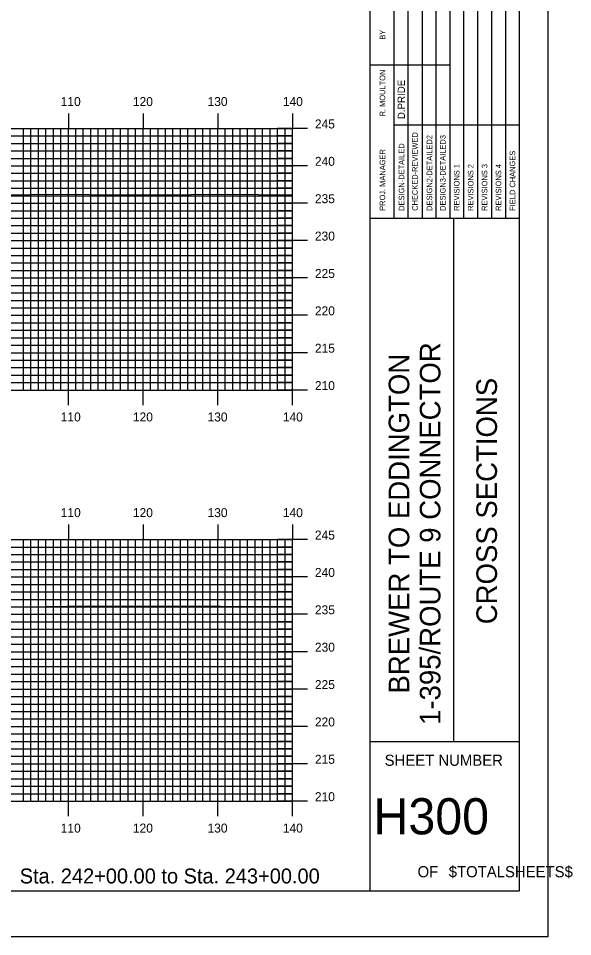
# Model space of a CAD drawing. Extents: x 1802323 to 1802666, y 442591 to 442811.
# Drawn here: x 1802591.9 to 1802666.1, y 442590.5 to 442713.4 of the extents above; entities that cross this region are included whole.
import ezdxf

# ---------------------------------------------------------------- set-up
doc = ezdxf.new("R2010")
doc.units = 0
for name, color, linetype in [('BORDER', 7, 'Continuous'), ('H_V ANNOTATION', 7, 'Continuous'), ('MAJOR', 7, 'Continuous'), ('MINOR', 7, 'Continuous'), ('PLOT BOUNDARY', 7, 'Continuous'), ('S_Roadway_Centerline', 7, 'Continuous')]:
    doc.layers.add(name, color=color, linetype=linetype)

msp = doc.modelspace()

# ---------------------------------------------------------------- linework, layer by layer
at = {"layer": 'BORDER'}
for p, q in [((1802639, 442596.67), (1802639, 442806.67)), ((1802639, 442686.67), (1802659, 442686.67)), ((1802650.18, 442616.67), (1802650.18, 442686.67)), ((1802639, 442616.67), (1802659, 442616.67))]:
    msp.add_line(p, q, dxfattribs=at)
msp.add_lwpolyline([(1802339, 442596.67), (1802659, 442596.67), (1802659, 442806.67), (1802339, 442806.67)], close=True, dxfattribs=at)
for points in [[(1802644.1, 442686.68), (1802644.1, 442721.67)], [(1802645.96, 442721.67), (1802645.96, 442686.68)], [(1802647.82, 442686.68), (1802647.82, 442721.67)], [(1802649.69, 442686.68), (1802649.69, 442721.67)], [(1802651.55, 442686.68), (1802651.55, 442721.67)], [(1802653.41, 442686.68), (1802653.41, 442721.67)], [(1802655.28, 442686.68), (1802655.28, 442721.67)], [(1802657.14, 442686.68), (1802657.14, 442721.67)], [(1802642.23, 442686.68), (1802642.23, 442720.26)], [(1802639, 442707.17), (1802642.23, 442707.17)], [(1802642.23, 442707.17), (1802649.68, 442707.17)], [(1802642.23, 442699.17), (1802659, 442699.17)]]:
    msp.add_lwpolyline(points, dxfattribs=at)
at = {"layer": 'MAJOR'}
for p, q in [((1802598.6, 442700.67), (1802598.6, 442698.67)), ((1802608.6, 442700.67), (1802608.6, 442698.67)), ((1802618.6, 442700.67), (1802618.6, 442698.67)), ((1802628.6, 442700.67), (1802628.6, 442698.67)), ((1802348.6, 442698.67), (1802628.6, 442698.67)), ((1802348.6, 442698.67), (1802628.6, 442698.67)), ((1802598.6, 442663.67), (1802598.6, 442698.67)), ((1802608.6, 442663.67), (1802608.6, 442698.67)), ((1802618.6, 442663.67), (1802618.6, 442698.67)), ((1802630.61, 442698.67), (1802626.6, 442698.67)), ((1802628.6, 442663.67), (1802628.6, 442698.67)), ((1802628.6, 442663.67), (1802628.6, 442698.67)), ((1802348.6, 442693.67), (1802628.6, 442693.67)), ((1802630.61, 442693.67), (1802626.6, 442693.67)), ((1802348.6, 442688.67), (1802628.6, 442688.67)), ((1802630.61, 442688.67), (1802626.6, 442688.67)), ((1802348.6, 442683.67), (1802628.6, 442683.67)), ((1802630.61, 442683.67), (1802626.6, 442683.67)), ((1802348.6, 442678.67), (1802628.6, 442678.67)), ((1802630.61, 442678.67), (1802626.6, 442678.67)), ((1802348.6, 442673.67), (1802628.6, 442673.67)), ((1802630.61, 442673.67), (1802626.6, 442673.67)), ((1802348.6, 442668.67), (1802628.6, 442668.67)), ((1802630.61, 442668.67), (1802626.6, 442668.67)), ((1802348.6, 442663.67), (1802628.6, 442663.67)), ((1802348.6, 442663.67), (1802628.6, 442663.67)), ((1802598.6, 442661.66), (1802598.6, 442663.67)), ((1802608.6, 442661.66), (1802608.6, 442663.67)), ((1802618.6, 442661.66), (1802618.6, 442663.67)), ((1802630.61, 442663.67), (1802626.6, 442663.67)), ((1802628.6, 442661.66), (1802628.6, 442663.67)), ((1802598.6, 442645.67), (1802598.6, 442643.67)), ((1802608.6, 442645.67), (1802608.6, 442643.67)), ((1802618.6, 442645.67), (1802618.6, 442643.67)), ((1802628.6, 442645.67), (1802628.6, 442643.67)), ((1802348.6, 442643.67), (1802628.6, 442643.67)), ((1802348.6, 442643.67), (1802628.6, 442643.67)), ((1802598.6, 442608.67), (1802598.6, 442643.67)), ((1802608.6, 442608.67), (1802608.6, 442643.67)), ((1802618.6, 442608.67), (1802618.6, 442643.67)), ((1802630.61, 442643.67), (1802626.6, 442643.67)), ((1802628.6, 442608.67), (1802628.6, 442643.67)), ((1802628.6, 442608.67), (1802628.6, 442643.67)), ((1802348.6, 442638.67), (1802628.6, 442638.67)), ((1802630.61, 442638.67), (1802626.6, 442638.67)), ((1802348.6, 442633.67), (1802628.6, 442633.67)), ((1802630.61, 442633.67), (1802626.6, 442633.67)), ((1802348.6, 442628.67), (1802628.6, 442628.67)), ((1802630.61, 442628.67), (1802626.6, 442628.67)), ((1802348.6, 442623.67), (1802628.6, 442623.67)), ((1802630.61, 442623.67), (1802626.6, 442623.67)), ((1802348.6, 442618.67), (1802628.6, 442618.67)), ((1802630.61, 442618.67), (1802626.6, 442618.67)), ((1802348.6, 442613.67), (1802628.6, 442613.67)), ((1802630.61, 442613.67), (1802626.6, 442613.67)), ((1802348.6, 442608.67), (1802628.6, 442608.67)), ((1802348.6, 442608.67), (1802628.6, 442608.67)), ((1802598.6, 442606.66), (1802598.6, 442608.67)), ((1802608.6, 442606.66), (1802608.6, 442608.67)), ((1802618.6, 442606.66), (1802618.6, 442608.67)), ((1802630.61, 442608.67), (1802626.6, 442608.67)), ((1802628.6, 442606.66), (1802628.6, 442608.67))]:
    msp.add_line(p, q, dxfattribs=at)
at = {"layer": 'MINOR'}
for p, q in [((1802592.6, 442663.67), (1802592.6, 442698.67)), ((1802593.6, 442663.67), (1802593.6, 442698.67)), ((1802594.6, 442663.67), (1802594.6, 442698.67)), ((1802595.6, 442663.67), (1802595.6, 442698.67)), ((1802596.6, 442663.67), (1802596.6, 442698.67)), ((1802597.6, 442663.67), (1802597.6, 442698.67)), ((1802599.6, 442663.67), (1802599.6, 442698.67)), ((1802600.6, 442663.67), (1802600.6, 442698.67)), ((1802601.6, 442663.67), (1802601.6, 442698.67)), ((1802602.6, 442663.67), (1802602.6, 442698.67)), ((1802603.6, 442663.67), (1802603.6, 442698.67)), ((1802604.6, 442663.67), (1802604.6, 442698.67)), ((1802605.6, 442663.67), (1802605.6, 442698.67)), ((1802606.6, 442663.67), (1802606.6, 442698.67)), ((1802607.6, 442663.67), (1802607.6, 442698.67)), ((1802609.6, 442663.67), (1802609.6, 442698.67)), ((1802610.6, 442663.67), (1802610.6, 442698.67)), ((1802611.6, 442663.67), (1802611.6, 442698.67)), ((1802612.6, 442663.67), (1802612.6, 442698.67)), ((1802613.6, 442663.67), (1802613.6, 442698.67)), ((1802614.6, 442663.67), (1802614.6, 442698.67)), ((1802615.6, 442663.67), (1802615.6, 442698.67)), ((1802616.6, 442663.67), (1802616.6, 442698.67)), ((1802617.6, 442663.67), (1802617.6, 442698.67)), ((1802619.6, 442663.67), (1802619.6, 442698.67)), ((1802620.6, 442663.67), (1802620.6, 442698.67)), ((1802621.6, 442663.67), (1802621.6, 442698.67)), ((1802622.6, 442663.67), (1802622.6, 442698.67)), ((1802623.6, 442663.67), (1802623.6, 442698.67)), ((1802624.6, 442663.67), (1802624.6, 442698.67)), ((1802625.6, 442663.67), (1802625.6, 442698.67)), ((1802626.6, 442663.67), (1802626.6, 442698.67)), ((1802627.6, 442663.67), (1802627.6, 442698.67)), ((1802348.6, 442697.67), (1802628.6, 442697.67)), ((1802628.6, 442697.67), (1802626.6, 442697.67)), ((1802348.6, 442696.67), (1802628.6, 442696.67)), ((1802628.6, 442696.67), (1802626.6, 442696.67)), ((1802348.6, 442695.67), (1802628.6, 442695.67)), ((1802628.6, 442695.67), (1802626.6, 442695.67)), ((1802348.6, 442694.67), (1802628.6, 442694.67)), ((1802628.6, 442694.67), (1802626.6, 442694.67)), ((1802348.6, 442692.67), (1802628.6, 442692.67)), ((1802628.6, 442692.67), (1802626.6, 442692.67)), ((1802348.6, 442691.67), (1802628.6, 442691.67)), ((1802628.6, 442691.67), (1802626.6, 442691.67)), ((1802348.6, 442690.67), (1802628.6, 442690.67)), ((1802628.6, 442690.67), (1802626.6, 442690.67)), ((1802348.6, 442689.67), (1802628.6, 442689.67)), ((1802628.6, 442689.67), (1802626.6, 442689.67)), ((1802348.6, 442687.67), (1802628.6, 442687.67)), ((1802628.6, 442687.67), (1802626.6, 442687.67)), ((1802348.6, 442686.67), (1802628.6, 442686.67)), ((1802628.6, 442686.67), (1802626.6, 442686.67)), ((1802348.6, 442685.67), (1802628.6, 442685.67)), ((1802628.6, 442685.67), (1802626.6, 442685.67)), ((1802348.6, 442684.67), (1802628.6, 442684.67)), ((1802628.6, 442684.67), (1802626.6, 442684.67)), ((1802348.6, 442682.67), (1802628.6, 442682.67)), ((1802628.6, 442682.67), (1802626.6, 442682.67)), ((1802348.6, 442681.67), (1802628.6, 442681.67)), ((1802628.6, 442681.67), (1802626.6, 442681.67)), ((1802348.6, 442680.67), (1802628.6, 442680.67)), ((1802628.6, 442680.67), (1802626.6, 442680.67)), ((1802348.6, 442679.67), (1802628.6, 442679.67)), ((1802628.6, 442679.67), (1802626.6, 442679.67)), ((1802348.6, 442677.67), (1802628.6, 442677.67)), ((1802628.6, 442677.67), (1802626.6, 442677.67)), ((1802348.6, 442676.67), (1802628.6, 442676.67)), ((1802628.6, 442676.67), (1802626.6, 442676.67)), ((1802348.6, 442675.67), (1802628.6, 442675.67)), ((1802628.6, 442675.67), (1802626.6, 442675.67)), ((1802348.6, 442674.67), (1802628.6, 442674.67)), ((1802628.6, 442674.67), (1802626.6, 442674.67)), ((1802348.6, 442672.67), (1802628.6, 442672.67)), ((1802628.6, 442672.67), (1802626.6, 442672.67)), ((1802348.6, 442671.67), (1802628.6, 442671.67)), ((1802628.6, 442671.67), (1802626.6, 442671.67)), ((1802348.6, 442670.67), (1802628.6, 442670.67)), ((1802628.6, 442670.67), (1802626.6, 442670.67)), ((1802348.6, 442669.67), (1802628.6, 442669.67)), ((1802628.6, 442669.67), (1802626.6, 442669.67)), ((1802348.6, 442667.67), (1802628.6, 442667.67)), ((1802348.6, 442666.67), (1802628.6, 442666.67)), ((1802628.6, 442667.67), (1802626.6, 442667.67)), ((1802628.6, 442666.67), (1802626.6, 442666.67)), ((1802348.6, 442665.67), (1802628.6, 442665.67)), ((1802628.6, 442665.67), (1802626.6, 442665.67)), ((1802348.6, 442664.67), (1802628.6, 442664.67)), ((1802628.6, 442664.67), (1802626.6, 442664.67)), ((1802592.6, 442608.67), (1802592.6, 442643.67)), ((1802593.6, 442608.67), (1802593.6, 442643.67)), ((1802594.6, 442608.67), (1802594.6, 442643.67)), ((1802595.6, 442608.67), (1802595.6, 442643.67)), ((1802596.6, 442608.67), (1802596.6, 442643.67)), ((1802597.6, 442608.67), (1802597.6, 442643.67)), ((1802599.6, 442608.67), (1802599.6, 442643.67)), ((1802600.6, 442608.67), (1802600.6, 442643.67)), ((1802601.6, 442608.67), (1802601.6, 442643.67)), ((1802602.6, 442608.67), (1802602.6, 442643.67)), ((1802603.6, 442608.67), (1802603.6, 442643.67)), ((1802604.6, 442608.67), (1802604.6, 442643.67)), ((1802605.6, 442608.67), (1802605.6, 442643.67)), ((1802606.6, 442608.67), (1802606.6, 442643.67)), ((1802607.6, 442608.67), (1802607.6, 442643.67)), ((1802609.6, 442608.67), (1802609.6, 442643.67)), ((1802610.6, 442608.67), (1802610.6, 442643.67)), ((1802611.6, 442608.67), (1802611.6, 442643.67)), ((1802612.6, 442608.67), (1802612.6, 442643.67)), ((1802613.6, 442608.67), (1802613.6, 442643.67)), ((1802614.6, 442608.67), (1802614.6, 442643.67)), ((1802615.6, 442608.67), (1802615.6, 442643.67)), ((1802616.6, 442608.67), (1802616.6, 442643.67)), ((1802617.6, 442608.67), (1802617.6, 442643.67)), ((1802619.6, 442608.67), (1802619.6, 442643.67)), ((1802620.6, 442608.67), (1802620.6, 442643.67)), ((1802621.6, 442608.67), (1802621.6, 442643.67)), ((1802622.6, 442608.67), (1802622.6, 442643.67)), ((1802623.6, 442608.67), (1802623.6, 442643.67)), ((1802624.6, 442608.67), (1802624.6, 442643.67)), ((1802625.6, 442608.67), (1802625.6, 442643.67)), ((1802626.6, 442608.67), (1802626.6, 442643.67)), ((1802627.6, 442608.67), (1802627.6, 442643.67)), ((1802348.6, 442642.67), (1802628.6, 442642.67)), ((1802628.6, 442642.67), (1802626.6, 442642.67)), ((1802348.6, 442641.67), (1802628.6, 442641.67)), ((1802628.6, 442641.67), (1802626.6, 442641.67)), ((1802348.6, 442640.67), (1802628.6, 442640.67)), ((1802348.6, 442639.67), (1802628.6, 442639.67)), ((1802628.6, 442640.67), (1802626.6, 442640.67)), ((1802628.6, 442639.67), (1802626.6, 442639.67)), ((1802348.6, 442637.67), (1802628.6, 442637.67)), ((1802628.6, 442637.67), (1802626.6, 442637.67)), ((1802348.6, 442636.67), (1802628.6, 442636.67)), ((1802628.6, 442636.67), (1802626.6, 442636.67)), ((1802348.6, 442635.67), (1802628.6, 442635.67)), ((1802348.6, 442634.67), (1802628.6, 442634.67)), ((1802628.6, 442635.67), (1802626.6, 442635.67)), ((1802628.6, 442634.67), (1802626.6, 442634.67)), ((1802348.6, 442632.67), (1802628.6, 442632.67)), ((1802628.6, 442632.67), (1802626.6, 442632.67)), ((1802348.6, 442631.67), (1802628.6, 442631.67)), ((1802628.6, 442631.67), (1802626.6, 442631.67)), ((1802348.6, 442630.67), (1802628.6, 442630.67)), ((1802628.6, 442630.67), (1802626.6, 442630.67)), ((1802348.6, 442629.67), (1802628.6, 442629.67)), ((1802628.6, 442629.67), (1802626.6, 442629.67)), ((1802348.6, 442627.67), (1802628.6, 442627.67)), ((1802628.6, 442627.67), (1802626.6, 442627.67)), ((1802348.6, 442626.67), (1802628.6, 442626.67)), ((1802628.6, 442626.67), (1802626.6, 442626.67)), ((1802348.6, 442625.67), (1802628.6, 442625.67)), ((1802628.6, 442625.67), (1802626.6, 442625.67)), ((1802348.6, 442624.67), (1802628.6, 442624.67)), ((1802628.6, 442624.67), (1802626.6, 442624.67)), ((1802348.6, 442622.67), (1802628.6, 442622.67)), ((1802628.6, 442622.67), (1802626.6, 442622.67)), ((1802348.6, 442621.67), (1802628.6, 442621.67)), ((1802628.6, 442621.67), (1802626.6, 442621.67)), ((1802348.6, 442620.67), (1802628.6, 442620.67)), ((1802628.6, 442620.67), (1802626.6, 442620.67)), ((1802348.6, 442619.67), (1802628.6, 442619.67)), ((1802628.6, 442619.67), (1802626.6, 442619.67)), ((1802348.6, 442617.67), (1802628.6, 442617.67)), ((1802628.6, 442617.67), (1802626.6, 442617.67)), ((1802348.6, 442616.67), (1802628.6, 442616.67)), ((1802628.6, 442616.67), (1802626.6, 442616.67)), ((1802348.6, 442615.67), (1802628.6, 442615.67)), ((1802628.6, 442615.67), (1802626.6, 442615.67)), ((1802348.6, 442614.67), (1802628.6, 442614.67)), ((1802628.6, 442614.67), (1802626.6, 442614.67)), ((1802348.6, 442612.67), (1802628.6, 442612.67)), ((1802628.6, 442612.67), (1802626.6, 442612.67)), ((1802348.6, 442611.67), (1802628.6, 442611.67)), ((1802628.6, 442611.67), (1802626.6, 442611.67)), ((1802348.6, 442610.67), (1802628.6, 442610.67)), ((1802628.6, 442610.67), (1802626.6, 442610.67)), ((1802348.6, 442609.67), (1802628.6, 442609.67)), ((1802628.6, 442609.67), (1802626.6, 442609.67))]:
    msp.add_line(p, q, dxfattribs=at)
at = {"layer": 'PLOT BOUNDARY'}
msp.add_lwpolyline([(1802322.81, 442590.55), (1802662.81, 442590.55), (1802662.81, 442810.55), (1802322.81, 442810.55)], close=True, dxfattribs=at)
at = {"layer": 'S_Roadway_Centerline'}
for points in [[(1802507.23, 442689.68), (1802521.77, 442689.85), (1802532.92, 442689.56), (1802542.65, 442689.58), (1802558.19, 442689.59), (1802561.43, 442689.59), (1802563.86, 442689.58), (1802573.13, 442689.67), (1802584.23, 442689.67), (1802585.29, 442689.69), (1802596.5, 442689.86), (1802606.34, 442689.81), (1802608.02, 442689.8), (1802610.12, 442689.78), (1802619.94, 442689.88), (1802628.21, 442689.81), (1802628.6, 442689.81)], [(1802516.07, 442634.75), (1802519.95, 442634.88), (1802523.24, 442635.01), (1802541.26, 442634.25), (1802543.67, 442634.08), (1802558.29, 442634.4), (1802565.52, 442634.56), (1802566.08, 442634.55), (1802566.8, 442634.53), (1802586.57, 442634.64), (1802588.92, 442634.72), (1802592.53, 442634.68), (1802601.35, 442634.81), (1802607.76, 442634.75), (1802618.96, 442634.77), (1802628.6, 442634.72)]]:
    msp.add_lwpolyline(points, dxfattribs=at)

# ---------------------------------------------------------------- texts
at = {"layer": 'BORDER'}
for s, height, p in [('BY', 0.743, (1802641.01, 442710.54)), ('R. MOULTON', 0.745, (1802641.01, 442700.28)), ('D.PRIDE', 0.969, (1802643.65, 442699.92)), ('CHECKED-REVIEWED', 0.7455, (1802645.36, 442687.65)), ('DESIGN2-DETAILED2', 0.7455, (1802647.3, 442687.65)), ('DESIGN3-DETAILED3', 0.7455, (1802649.09, 442687.65)), ('DESIGN-DETAILED', 0.7455, (1802643.57, 442687.65)), ('PROJ. MANAGER', 0.7455, (1802641.01, 442687.65)), ('FIELD CHANGES', 0.7455, (1802658.41, 442687.65)), ('REVISIONS 1', 0.7455, (1802650.95, 442687.65)), ('REVISIONS 2', 0.7455, (1802652.82, 442687.65)), ('REVISIONS 3', 0.7455, (1802654.68, 442687.65)), ('REVISIONS 4', 0.7455, (1802656.54, 442687.65)), ('1-395/ROUTE 9 CONNECTOR', 2.7557, (1802648.4, 442618.87)), ('BREWER TO EDDINGTON', 2.7557, (1802644.23, 442623.07)), ('CROSS SECTIONS', 2.7557, (1802655.97, 442632.34))]:
    msp.add_text(s, height=height, rotation=90, dxfattribs=at).set_placement(p)
for s, height, p in [('SHEET NUMBER', 1.4905, (1802640.93, 442613.4)), ('H300', 4.839, (1802639.44, 442604.23)), ('OF', 1.491, (1802645.34, 442598.49)), ('$TOTALSHEETS$', 1.4905, (1802649.51, 442598.49))]:
    msp.add_text(s, height=height, dxfattribs=at).set_placement(p)
at = {"layer": 'H_V ANNOTATION'}
for s, height, p in [('110', 1.2, (1802597.58, 442701.67)), ('120', 1.2, (1802607.24, 442701.67)), ('130', 1.2, (1802617.23, 442701.67)), ('140', 1.2, (1802627.31, 442701.67)), ('245', 1.2, (1802631.6, 442698.67)), ('240', 1.2, (1802631.6, 442693.67)), ('235', 1.2, (1802631.6, 442688.67)), ('230', 1.2, (1802631.6, 442683.67)), ('225', 1.2, (1802631.6, 442678.67)), ('220', 1.2, (1802631.6, 442673.67)), ('215', 1.2, (1802631.6, 442668.67)), ('210', 1.2, (1802631.6, 442663.67)), ('110', 1.2, (1802597.58, 442659.47)), ('120', 1.2, (1802607.24, 442659.47)), ('130', 1.2, (1802617.23, 442659.47)), ('140', 1.2, (1802627.31, 442659.47)), ('110', 1.2, (1802597.58, 442646.67)), ('120', 1.2, (1802607.24, 442646.67)), ('130', 1.2, (1802617.23, 442646.67)), ('140', 1.2, (1802627.31, 442646.67)), ('245', 1.2, (1802631.6, 442643.67)), ('240', 1.2, (1802631.6, 442638.67)), ('235', 1.2, (1802631.6, 442633.67)), ('230', 1.2, (1802631.6, 442628.67)), ('225', 1.2, (1802631.6, 442623.67)), ('220', 1.2, (1802631.6, 442618.67)), ('215', 1.2, (1802631.6, 442613.67)), ('210', 1.2, (1802631.6, 442608.67)), ('110', 1.2, (1802597.58, 442604.47)), ('120', 1.2, (1802607.24, 442604.47)), ('130', 1.2, (1802617.23, 442604.47)), ('140', 1.2, (1802627.31, 442604.47)), ('Sta. 242+00.00 to Sta. 243+00.00', 2.0004, (1802592.09, 442597.66))]:
    msp.add_text(s, height=height, dxfattribs=at).set_placement(p)

doc.saveas('drawing.dxf')
